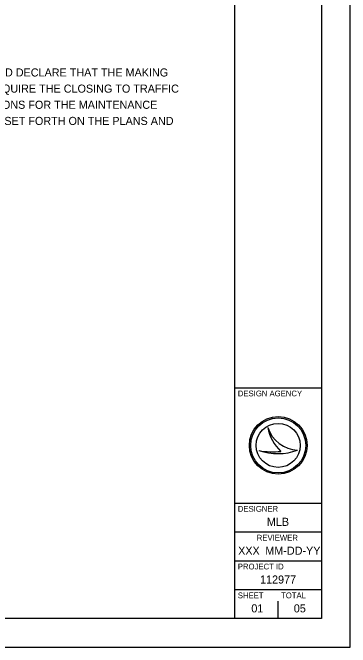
# Model space of a CAD drawing. Extents: x 0 to 34, y 0 to 22.
# Drawn here: x 28.15 to 34, y 0 to 11 of the extents above; entities that cross this region are included whole.
import ezdxf

# ---------------------------------------------------------------- set-up
doc = ezdxf.new("R2010")
doc.units = 0
for name, color, linetype in [('SH_Border', 7, 'Continuous'), ('SH_Cut_Line', 7, 'Continuous'), ('SH_Data', 7, 'Continuous'), ('SH_Text', 7, 'Continuous')]:
    doc.layers.add(name, color=color, linetype=linetype)

msp = doc.modelspace()

# ---------------------------------------------------------------- linework, layer by layer
at = {"layer": 'SH_Border'}
for p, q in [((32, 0.498), (32, 21.498)), ((32, 4.498), (33.5, 4.498)), ((32, 2.498), (33.5, 2.498)), ((32, 1.998), (33.5, 1.998)), ((32, 1.498), (33.5, 1.498)), ((32, 0.998), (33.5, 0.998))]:
    msp.add_line(p, q, dxfattribs=at)
msp.add_lwpolyline([(1.5, 21.498), (33.5, 21.498), (33.5, 0.498), (1.5, 0.498)], close=True, dxfattribs=at)
at = {"layer": 'SH_Cut_Line'}
msp.add_lwpolyline([(0, -0.002), (34, -0.002), (34, 21.998), (0, 21.998)], close=True, dxfattribs=at)
at = {"layer": 'SH_Data'}
for p, q in [((32.567, 3.808), (32.567, 3.808)), ((32.75, 3.498), (32.75, 3.498)), ((33.087, 3.417), (33.087, 3.417)), ((32.417, 3.408), (32.417, 3.408)), ((32.75, 0.498), (32.75, 0.798)), ((32.375, 0.673), (32.375, 0.673))]:
    msp.add_line(p, q, dxfattribs=at)
for radius in [0.5, 0.477, 0.477, 0.382]:
    msp.add_circle((32.75, 3.498), radius, dxfattribs=at)
for centre, radius, start, end in [((33.116, 3.996), 0.58, 198.9257, 198.9319), ((33.347, 3.968), 0.796, 191.6379, 191.6421), ((33.116, 3.996), 0.58, 198.9319, 267.1657), ((33.347, 3.968), 0.796, 191.6421, 226.0947), ((32.739, 4.368), 1.013, 251.4576, 290.0832), ((32.648, 4.652), 1.266, 259.4964, 259.4995), ((32.739, 4.368), 1.013, 251.4527, 251.4576), ((32.648, 4.652), 1.266, 259.4995, 276.6672)]:
    msp.add_arc(centre, radius, start, end, dxfattribs=at)

# ---------------------------------------------------------------- texts
for s, height, p in [('DESIGN AGENCY', 0.1, (32.05, 4.348)), ('DESIGNER', 0.1, (32.05, 2.348)), ('MLB', 0.14, (32.554, 2.103)), ('REVIEWER', 0.1, (32.378, 1.848)), ('XXX', 0.14, (32.055, 1.603)), ('MM-DD-YY', 0.14, (32.526, 1.603)), ('PROJECT ID', 0.1, (32.05, 1.348)), ('112977', 0.14, (32.435, 1.103)), ('SHEET', 0.1, (32.05, 0.848)), ('TOTAL', 0.1, (32.8, 0.848)), ('01', 0.14, (32.284, 0.603)), ('05', 0.14, (33.02, 0.603))]:
    msp.add_text(s, height=height, dxfattribs=at).set_placement(p)
at = {"layer": 'SH_Text'}
for s, p in [('I HEREBY APPROVE THESE PLANS AND DECLARE THAT THE MAKING ', (24.528, 9.892)), ('OF THIS IMPROVEMENT WILL NOT REQUIRE THE CLOSING TO TRAFFIC ', (24.528, 9.612)), ('OF THE HIGHWAY AND THAT PROVISIONS FOR THE MAINTENANCE ', (24.528, 9.332)), ('AND SAFETY OF TRAFFIC WILL BE AS SET FORTH ON THE PLANS AND ', (24.528, 9.052))]:
    msp.add_text(s, height=0.14, dxfattribs=at).set_placement(p)

doc.saveas('drawing.dxf')
